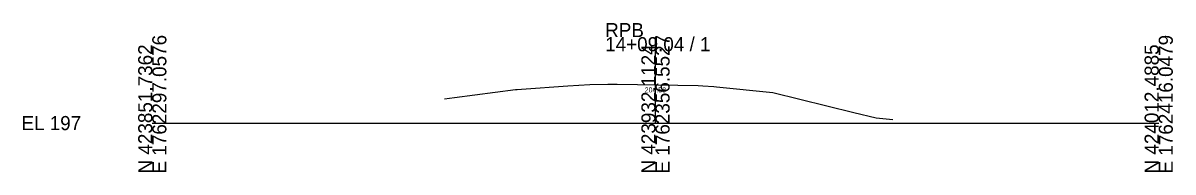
# Model space of a CAD drawing. Extents: x -26 to 203, y -10 to 4520.
# Drawn here: x -25.7 to 202.8, y 4490.3 to 4519.8 of the extents above; entities that cross this region are included whole.
import ezdxf

# ---------------------------------------------------------------- set-up
doc = ezdxf.new("R2010")
doc.units = 0
for name, color, linetype in [('Default', 7, 'Continuous'), ('Exist Cross Section Cell', 7, 'Continuous'), ('Exist XS Center Line Elevation Label', 7, 'Continuous'), ('Exist XS Ground Line', 7, 'Continuous')]:
    doc.layers.add(name, color=color, linetype=linetype)

msp = doc.modelspace()

# ---------------------------------------------------------------- linework, layer by layer
at = {"layer": 'Exist Cross Section Cell'}
for p, q in [((100, 4500), (100, 4517.04)), ((0, 4500), (100, 4500)), ((100, 4500), (200, 4500))]:
    msp.add_line(p, q, dxfattribs=at)
at = {"layer": 'Exist XS Ground Line'}
msp.add_lwpolyline([(58.06, 4504.79), (60.05, 4505.07), (72.18, 4506.65), (72.36, 4506.67), (72.49, 4506.69), (73.37, 4506.74), (82.58, 4507.36), (86.94, 4507.63), (90.55, 4507.73), (92.38, 4507.7), (108.45, 4507.45), (109.42, 4507.39), (111.56, 4507.23), (111.59, 4507.23), (111.59, 4507.23), (111.59, 4507.23), (112.15, 4507.18), (123.33, 4506.08), (139.41, 4502.1), (143.85, 4501.05), (147.14, 4500.68)], dxfattribs=at)
msp.add_lwpolyline([(58.06, 4504.79), (60.05, 4505.07), (72.18, 4506.65), (72.36, 4506.67), (72.49, 4506.69), (73.37, 4506.74), (82.58, 4507.36), (86.94, 4507.63), (90.55, 4507.73), (92.38, 4507.7), (108.45, 4507.45), (109.42, 4507.39), (111.56, 4507.23), (111.59, 4507.23), (111.59, 4507.23), (111.59, 4507.23), (112.15, 4507.18), (123.33, 4506.08), (139.41, 4502.1), (143.85, 4501.05), (147.14, 4500.68)], dxfattribs=at)

# ---------------------------------------------------------------- texts
at = {"layer": 'Default'}
msp.add_text('-', height=0.0001, dxfattribs=at).set_placement((0, 4500))
at = {"layer": 'Exist Cross Section Cell'}
for s, p in [('RPB', (90, 4517.04)), ('14+09.04 / 1', (90, 4514.24)), ('EL 197', (-26, 4498.6))]:
    msp.add_text(s, height=2.8, dxfattribs=at).set_placement(p)
for s, p in [('E 1762297.0576', (2.8, 4490)), ('E 1762356.5527', (102.8, 4490)), ('E 1762416.0479', (202.8, 4490)), ('N 423851.7362', (0, 4490)), ('N 423932.1124', (100, 4490)), ('N 424012.4885', (200, 4490))]:
    msp.add_text(s, height=2.8, rotation=90, dxfattribs=at).set_placement(p)
at = {"layer": 'Exist XS Center Line Elevation Label'}
msp.add_text('204.58', height=1, dxfattribs=at).set_placement((97.86, 4506.08))

doc.saveas('drawing.dxf')
